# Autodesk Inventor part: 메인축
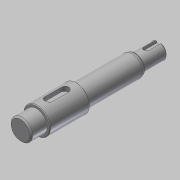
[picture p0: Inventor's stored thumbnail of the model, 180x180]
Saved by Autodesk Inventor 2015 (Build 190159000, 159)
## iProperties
Created: 2019-03
Part Number: 메인축
Material: 강철, 연강
Document SubType Name: Modeling
Designer: mduedu
Density: 1 g/cm^3
Appearance: 강철
Author: mduedu
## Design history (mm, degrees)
sketch "스케치1"
  geometry: L1 (0, 0)-(12, 0); L2 (12, 0)-(12, 8); L3 (12, 8)-(0, 8); L4 (0, 8)-(0, 0); L5 (12, 0)-(42, 0); L6 (42, 0)-(42, 10); L7 (42, 10)-(12, 10); L8 (12, 10)-(12, 0); L9 (42, 0)-(86, 0); L10 (86, 0)-(86, 8); L11 (86, 8)-(42, 8); L12 (42, 8)-(42, 0); L13 (86, 0)-(104, 0); L14 (104, 0)-(104, 6); L15 (104, 6)-(86, 6); L16 (86, 6)-(86, 0)
  constraints: 32 end point, 8 parallel, 4 horizontal, 4 perpendicular
  dimensions: "d0" = 16 diameter of L3 L1; "d2" = 20 diameter of L7 L5; "d3" = 16 diameter of L11 L9; "d4" = 12 diameter of L15 L13; "d5" = 12 distance of L2.end L3.end; "d6" = 30 distance of L6.end L7.end; "d7" = 86 distance between parallel lines of L10 L4; "d8" = 104 distance between parallel lines of L14 L4
revolve "회전1" sketch "스케치1" stored, may be unused: angle "d9" = 90 deg
node "작업 평면1"
sketch "스케치2" dims "d10" = 18
  geometry: L1 (6, -3)-(-6, -3); L2 (-6, -3)-(-6, 3); L3 (-6, 3)-(6, 3); L4 (6, 3)-(6, -3); L5 (15, 10)-(15, -10) reference; 3 further points
  constraints: 8 end point, 2 midpoint, 2 parallel, 2 vertical alignment, 1 horizontal, 1 horizontal alignment, 1 perpendicular, 4 other
  dimensions: "d12" = 6 distance between parallel lines of L3 L1; "d13" = 6 dimension on L5
extrude "돌출1" cut sketch "스케치2" distance "d14" = 3.5; taper "d15" = 0 deg
node "작업 평면2"
sketch "스케치3"
  geometry: L1 (-9, 6)-(-9, -6) reference; L2 (1, -2)-(-9, -2); L3 (1, 2)-(-9, 2); A1 r 2 centre (1, 0) between (1, -2) and (1, 2); 2 further points
  constraints: 4 end point, 2 point on circle, 2 point on line, 2 tangent, 1 centre point, 1 horizontal alignment, 1 midpoint, 1 parallel, 1 perpendicular
  dimensions: "d16" = 12 dimension on A1 L1; "d17" = 4 distance between parallel lines of L3 L2
extrude "돌출2" cut sketch "스케치3" distance "d18" = 2.5; taper "d19" = 0 deg
chamfer "모따기1" distance "d20" = 1; stored, may be unused: second distance "d21" = 2, angle "d22" = 45 deg
chamfer "모따기2" distance "d23" = 0.5; stored, may be unused: second distance "d24" = 2, angle "d25" = 45 deg
chamfer "모따기3" distance "d26" = 1.73; stored, may be unused: second distance "d27" = 2, angle "d28" = 30 deg
fillet "모깎기2" dims "d31" = 0.5, "d32" = 4
node "솔리드1"
